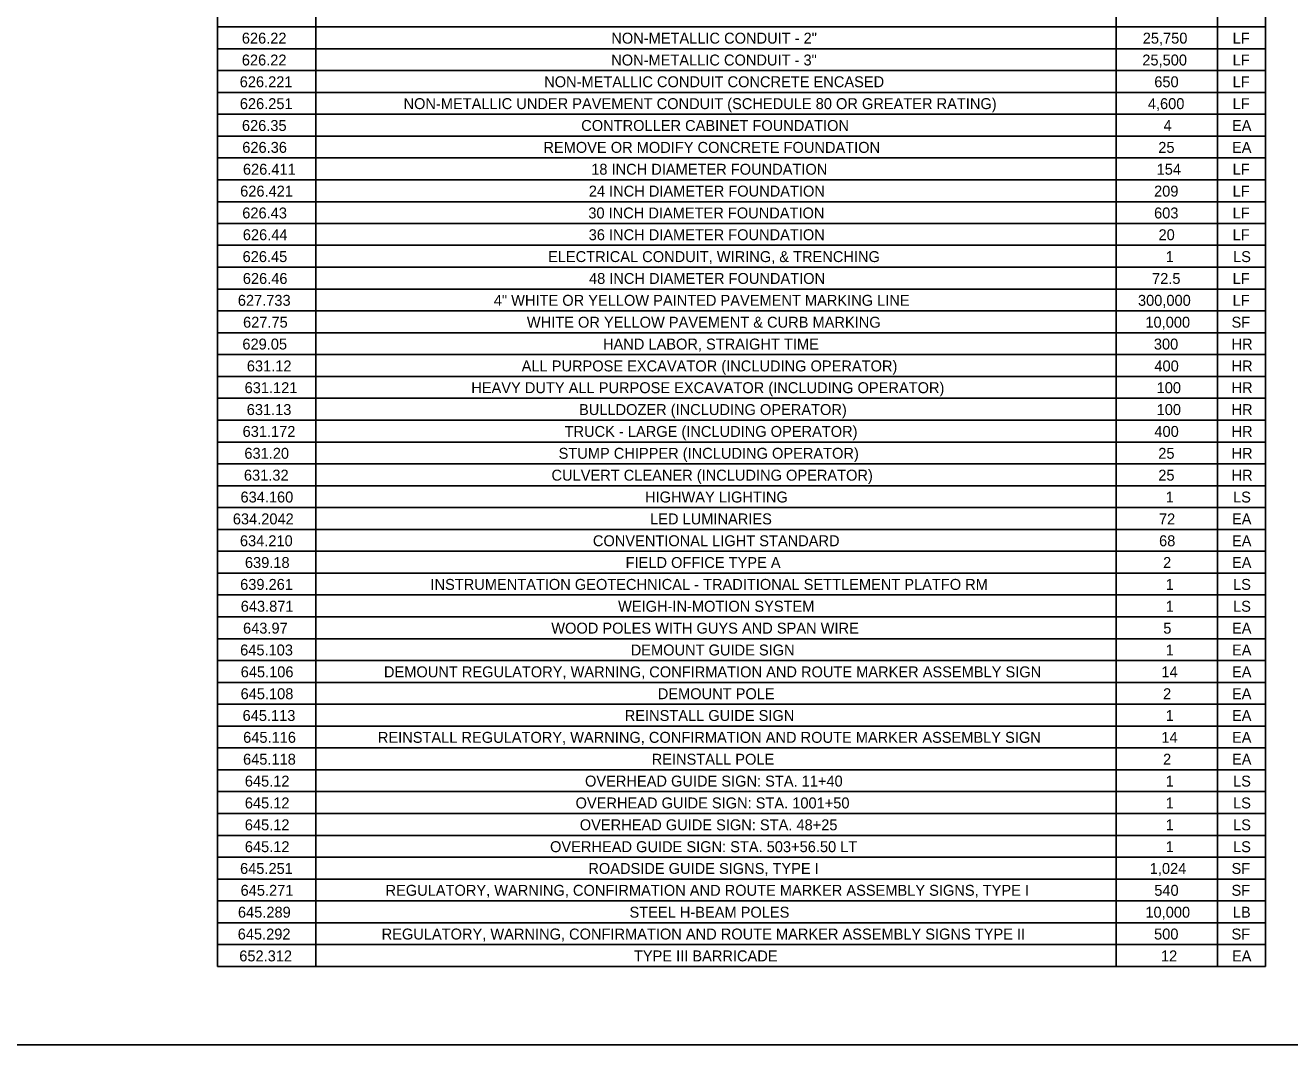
# Model space of a CAD drawing. Extents: x -18.7 to 5.6, y -2.7 to 4.
# Drawn here: x -15.505 to -14.366, y 2.172 to 3.09 of the extents above; entities that cross this region are included whole.
import ezdxf

# ---------------------------------------------------------------- set-up
doc = ezdxf.new("R2010")
doc.units = 0
doc.layers.add('ANNOTATION', color=7, linetype='Continuous')
doc.layers.add('BORDER', color=7, linetype='Continuous')

msp = doc.modelspace()

# ---------------------------------------------------------------- linework, layer by layer
at = {"layer": 'ANNOTATION'}
msp.add_lwpolyline([(-17.663, 4.0141), (-13.3075, 4.0141), (-13.3075, 2.1719), (-17.663, 2.1719)], close=True, dxfattribs=at)
at = {"layer": 'BORDER'}
for p, q in [((-15.2435, 3.9551), (-15.2435, 2.2424)), ((-14.5222, 3.9551), (-14.5222, 2.2424)), ((-14.4308, 3.9551), (-14.4308, 2.2424)), ((-15.3321, 3.0889), (-14.3878, 3.0889)), ((-15.3321, 3.0692), (-14.3878, 3.0692)), ((-15.3321, 3.0495), (-14.3878, 3.0495)), ((-15.3321, 3.0299), (-14.3878, 3.0299)), ((-15.3321, 3.0102), (-14.3878, 3.0102)), ((-15.3321, 2.9905), (-14.3878, 2.9905)), ((-15.3321, 2.9708), (-14.3878, 2.9708)), ((-15.3321, 2.9511), (-14.3878, 2.9511)), ((-15.3321, 2.9314), (-14.3878, 2.9314)), ((-15.3321, 2.9117), (-14.3878, 2.9117)), ((-15.3321, 2.8921), (-14.3878, 2.8921)), ((-15.3321, 2.8724), (-14.3878, 2.8724)), ((-15.3321, 2.8527), (-14.3878, 2.8527)), ((-15.3321, 2.833), (-14.3878, 2.833)), ((-15.3321, 2.8133), (-14.3878, 2.8133)), ((-15.3321, 2.7936), (-14.3878, 2.7936)), ((-15.3321, 2.7739), (-14.3878, 2.7739)), ((-15.3321, 2.7543), (-14.3878, 2.7543)), ((-15.3321, 2.7346), (-14.3878, 2.7346)), ((-15.3321, 2.7149), (-14.3878, 2.7149)), ((-15.3321, 2.6952), (-14.3878, 2.6952)), ((-15.3321, 2.6755), (-14.3878, 2.6755)), ((-15.3321, 2.6558), (-14.3878, 2.6558)), ((-15.3321, 2.6361), (-14.3878, 2.6361)), ((-15.3321, 2.6165), (-14.3878, 2.6165)), ((-15.3321, 2.5968), (-14.3878, 2.5968)), ((-15.3321, 2.5771), (-14.3878, 2.5771)), ((-15.3321, 2.5574), (-14.3878, 2.5574)), ((-15.3321, 2.5377), (-14.3878, 2.5377)), ((-15.3321, 2.518), (-14.3878, 2.518)), ((-15.3321, 2.4983), (-14.3878, 2.4983)), ((-15.3321, 2.4787), (-14.3878, 2.4787)), ((-15.3321, 2.459), (-14.3878, 2.459)), ((-15.3321, 2.4393), (-14.3878, 2.4393)), ((-15.3321, 2.4196), (-14.3878, 2.4196)), ((-15.3321, 2.3999), (-14.3878, 2.3999)), ((-15.3321, 2.3802), (-14.3878, 2.3802)), ((-15.3321, 2.3605), (-14.3878, 2.3605)), ((-15.3321, 2.3408), (-14.3878, 2.3408)), ((-15.3321, 2.3212), (-14.3878, 2.3212)), ((-15.3321, 2.3015), (-14.3878, 2.3015)), ((-15.3321, 2.2818), (-14.3878, 2.2818)), ((-15.3321, 2.2621), (-14.3878, 2.2621)), ((-15.3321, 2.2424), (-14.3878, 2.2424))]:
    msp.add_line(p, q, dxfattribs=at)
msp.add_lwpolyline([(-15.3321, 3.9748), (-14.3878, 3.9748), (-14.3878, 2.2424), (-15.3321, 2.2424)], close=True, dxfattribs=at)

# ---------------------------------------------------------------- texts
at = {"layer": 'ANNOTATION'}
for s, height, p in [('626.22', 0.00984, (-15.3103, 3.0738)), ('NON-METALLIC CONDUIT - 2"', 0.009843, (-14.9773, 3.0738)), ('25,750', 0.00984, (-14.4983, 3.0738)), ('LF', 0.00984, (-14.4173, 3.0738)), ('626.22', 0.00984, (-15.3103, 3.0541)), ('NON-METALLIC CONDUIT - 3"', 0.009843, (-14.9774, 3.0541)), ('25,500', 0.00984, (-14.4987, 3.0541)), ('LF', 0.00984, (-14.4173, 3.0541)), ('626.221', 0.00984, (-15.3122, 3.0345)), ('NON-METALLIC CONDUIT CONCRETE ENCASED', 0.009843, (-15.0378, 3.0345)), ('650', 0.00984, (-14.4879, 3.0345)), ('LF', 0.00984, (-14.4173, 3.0345)), ('626.251', 0.00984, (-15.3121, 3.0148)), ('NON-METALLIC UNDER PAVEMENT CONDUIT (SCHEDULE 80 OR GREATER RATING)', 0.009843, (-15.1646, 3.0148)), ('4,600', 0.00984, (-14.4937, 3.0148)), ('LF', 0.00984, (-14.4173, 3.0148)), ('626.35', 0.00984, (-15.3102, 2.9951)), ('CONTROLLER CABINET FOUNDATION', 0.009843, (-15.0044, 2.9951)), ('4', 0.00984, (-14.4796, 2.9951)), ('EA', 0.00984, (-14.4179, 2.9951)), ('626.36', 0.00984, (-15.3099, 2.9754)), ('REMOVE OR MODIFY CONCRETE FOUNDATION', 0.009843, (-15.0385, 2.9754)), ('25', 0.00984, (-14.4843, 2.9754)), ('EA', 0.00984, (-14.4179, 2.9754)), ('626.411', 0.00984, (-15.3093, 2.9557)), ('18 INCH DIAMETER FOUNDATION', 0.009843, (-14.9954, 2.9557)), ('154', 0.00984, (-14.4858, 2.9557)), ('LF', 0.00984, (-14.4173, 2.9557)), ('626.421', 0.00984, (-15.3118, 2.936)), ('24 INCH DIAMETER FOUNDATION', 0.009843, (-14.9976, 2.936)), ('209', 0.00984, (-14.4881, 2.936)), ('LF', 0.00984, (-14.4173, 2.936)), ('626.43', 0.00984, (-15.3099, 2.9163)), ('30 INCH DIAMETER FOUNDATION', 0.009843, (-14.998, 2.9163)), ('603', 0.00984, (-14.4881, 2.9163)), ('LF', 0.00984, (-14.4173, 2.9163)), ('626.44', 0.00984, (-15.3094, 2.8967)), ('36 INCH DIAMETER FOUNDATION', 0.009843, (-14.9977, 2.8967)), ('20', 0.00984, (-14.4841, 2.8967)), ('LF', 0.00984, (-14.4173, 2.8967)), ('626.45', 0.00984, (-15.3096, 2.877)), ('ELECTRICAL CONDUIT, WIRING, & TRENCHING', 0.009843, (-15.0343, 2.877)), ('1', 0.00984, (-14.4776, 2.877)), ('LS', 0.00984, (-14.4169, 2.877)), ('626.46', 0.00984, (-15.3094, 2.8573)), ('48 INCH DIAMETER FOUNDATION', 0.009843, (-14.9974, 2.8573)), ('72.5', 0.00984, (-14.4899, 2.8573)), ('LF', 0.00984, (-14.4173, 2.8573)), ('627.733', 0.00984, (-15.3139, 2.8376)), ('4" WHITE OR YELLOW PAINTED PAVEMENT MARKING LINE', 0.009843, (-15.0832, 2.8376)), ('300,000', 0.00984, (-14.5026, 2.8376)), ('LF', 0.00984, (-14.4173, 2.8376)), ('627.75', 0.00984, (-15.3092, 2.8179)), ('WHITE OR YELLOW PAVEMENT & CURB MARKING', 0.009843, (-15.0534, 2.8179)), ('10,000', 0.00984, (-14.4959, 2.8179)), ('SF', 0.00984, (-14.4183, 2.8179)), ('629.05', 0.00984, (-15.3098, 2.7982)), ('HAND LABOR, STRAIGHT TIME', 0.009843, (-14.9848, 2.7982)), ('300', 0.00984, (-14.4883, 2.7982)), ('HR', 0.00984, (-14.4183, 2.7982)), ('631.12', 0.00984, (-15.3058, 2.7785)), ('ALL PURPOSE EXCAVATOR (INCLUDING OPERATOR)', 0.009843, (-15.0581, 2.7785)), ('400', 0.00984, (-14.4878, 2.7785)), ('HR', 0.00984, (-14.4183, 2.7785)), ('631.121', 0.00984, (-15.3078, 2.7589)), ('HEAVY DUTY ALL PURPOSE EXCAVATOR (INCLUDING OPERATOR)', 0.009843, (-15.1035, 2.7589)), ('100', 0.00984, (-14.4858, 2.7589)), ('HR', 0.00984, (-14.4183, 2.7589)), ('631.13', 0.00984, (-15.3059, 2.7392)), ('BULLDOZER (INCLUDING OPERATOR)', 0.009843, (-15.0064, 2.7392)), ('100', 0.00984, (-14.4858, 2.7392)), ('HR', 0.00984, (-14.4183, 2.7392)), ('631.172', 0.00984, (-15.3096, 2.7195)), ('TRUCK - LARGE (INCLUDING OPERATOR)', 0.009843, (-15.0194, 2.7195)), ('400', 0.00984, (-14.4878, 2.7195)), ('HR', 0.00984, (-14.4183, 2.7195)), ('631.20', 0.00984, (-15.308, 2.6998)), ('STUMP CHIPPER (INCLUDING OPERATOR)', 0.009843, (-15.0248, 2.6998)), ('25', 0.00984, (-14.4843, 2.6998)), ('HR', 0.00984, (-14.4183, 2.6998)), ('631.32', 0.00984, (-15.3084, 2.6801)), ('CULVERT CLEANER (INCLUDING OPERATOR)', 0.009843, (-15.0312, 2.6801)), ('25', 0.00984, (-14.4843, 2.6801)), ('HR', 0.00984, (-14.4183, 2.6801)), ('634.160', 0.00984, (-15.3115, 2.6604)), ('HIGHWAY LIGHTING', 0.009843, (-14.9469, 2.6604)), ('1', 0.00984, (-14.4776, 2.6604)), ('LS', 0.00984, (-14.4169, 2.6604)), ('634.2042', 0.00984, (-15.3184, 2.6407)), ('LED LUMINARIES', 0.009843, (-14.9423, 2.6407)), ('72', 0.00984, (-14.4837, 2.6407)), ('EA', 0.00984, (-14.4179, 2.6407)), ('634.210', 0.00984, (-15.312, 2.621)), ('CONVENTIONAL LIGHT STANDARD', 0.009843, (-14.9939, 2.621)), ('68', 0.00984, (-14.4836, 2.621)), ('EA', 0.00984, (-14.4179, 2.621)), ('639.18', 0.00984, (-15.3075, 2.6014)), ('FIELD OFFICE TYPE A', 0.009843, (-14.9644, 2.6014)), ('2', 0.00984, (-14.48, 2.6014)), ('EA', 0.00984, (-14.4179, 2.6014)), ('639.261', 0.00984, (-15.3118, 2.5817)), ('INSTRUMENTATION GEOTECHNICAL - TRADITIONAL SETTLEMENT PLATFO RM', 0.009843, (-15.1403, 2.5817)), ('1', 0.00984, (-14.4776, 2.5817)), ('LS', 0.00984, (-14.4169, 2.5817)), ('643.871', 0.00984, (-15.3113, 2.562)), ('WEIGH-IN-MOTION SYSTEM', 0.009843, (-14.9712, 2.562)), ('1', 0.00984, (-14.4776, 2.562)), ('LS', 0.00984, (-14.4169, 2.562)), ('643.97', 0.00984, (-15.3092, 2.5423)), ('WOOD POLES WITH GUYS AND SPAN WIRE', 0.009843, (-15.0314, 2.5423)), ('5', 0.00984, (-14.4798, 2.5423)), ('EA', 0.00984, (-14.4179, 2.5423)), ('645.103', 0.00984, (-15.3118, 2.5226)), ('DEMOUNT GUIDE SIGN', 0.009843, (-14.9598, 2.5226)), ('1', 0.00984, (-14.4776, 2.5226)), ('EA', 0.00984, (-14.4179, 2.5226)), ('645.106', 0.00984, (-15.3113, 2.5029)), ('DEMOUNT REGULATORY, WARNING, CONFIRMATION AND ROUTE MARKER ASSEMBLY SIGN', 0.009843, (-15.1822, 2.5029)), ('14', 0.00984, (-14.4815, 2.5029)), ('EA', 0.00984, (-14.4179, 2.5029)), ('645.108', 0.00984, (-15.3114, 2.4832)), ('DEMOUNT POLE', 0.009843, (-14.9354, 2.4832)), ('2', 0.00984, (-14.48, 2.4832)), ('EA', 0.00984, (-14.4179, 2.4832)), ('645.113', 0.00984, (-15.3096, 2.4636)), ('REINSTALL GUIDE SIGN', 0.009843, (-14.9652, 2.4636)), ('1', 0.00984, (-14.4776, 2.4636)), ('EA', 0.00984, (-14.4179, 2.4636)), ('645.116', 0.00984, (-15.3091, 2.4439)), ('REINSTALL REGULATORY, WARNING, CONFIRMATION AND ROUTE MARKER ASSEMBLY SIGN', 0.009843, (-15.1877, 2.4439)), ('14', 0.00984, (-14.4815, 2.4439)), ('EA', 0.00984, (-14.4179, 2.4439)), ('645.118', 0.00984, (-15.3092, 2.4242)), ('REINSTALL POLE', 0.009843, (-14.9409, 2.4242)), ('2', 0.00984, (-14.48, 2.4242)), ('EA', 0.00984, (-14.4179, 2.4242)), ('645.12', 0.00984, (-15.3076, 2.4045)), ('OVERHEAD GUIDE SIGN: STA. 11+40', 0.009843, (-15.001, 2.4045)), ('1', 0.00984, (-14.4776, 2.4045)), ('LS', 0.00984, (-14.4169, 2.4045)), ('645.12', 0.00984, (-15.3076, 2.3848)), ('OVERHEAD GUIDE SIGN: STA. 1001+50', 0.009843, (-15.0095, 2.3848)), ('1', 0.00984, (-14.4776, 2.3848)), ('LS', 0.00984, (-14.4169, 2.3848)), ('645.12', 0.00984, (-15.3076, 2.3651)), ('OVERHEAD GUIDE SIGN: STA. 48+25', 0.009843, (-15.0057, 2.3651)), ('1', 0.00984, (-14.4776, 2.3651)), ('LS', 0.00984, (-14.4169, 2.3651)), ('645.12', 0.00984, (-15.3076, 2.3454)), ('OVERHEAD GUIDE SIGN: STA. 503+56.50 LT', 0.009843, (-15.0325, 2.3454)), ('1', 0.00984, (-14.4776, 2.3454)), ('LS', 0.00984, (-14.4169, 2.3454)), ('645.251', 0.00984, (-15.3119, 2.3258)), ('ROADSIDE GUIDE SIGNS, TYPE I', 0.009843, (-14.998, 2.3258)), ('1,024', 0.00984, (-14.492, 2.3258)), ('SF', 0.00984, (-14.4183, 2.3258)), ('645.271', 0.00984, (-15.3114, 2.3061)), ('REGULATORY, WARNING, CONFIRMATION AND ROUTE MARKER ASSEMBLY SIGNS, TYPE I', 0.009843, (-15.1808, 2.3061)), ('540', 0.00984, (-14.4879, 2.3061)), ('SF', 0.00984, (-14.4183, 2.3061)), ('645.289', 0.00984, (-15.3138, 2.2864)), ('STEEL H-BEAM POLES', 0.009843, (-14.9609, 2.2864)), ('10,000', 0.00984, (-14.4959, 2.2864)), ('LB', 0.00984, (-14.4171, 2.2864)), ('645.292', 0.00984, (-15.314, 2.2667)), ('REGULATORY, WARNING, CONFIRMATION AND ROUTE MARKER ASSEMBLY SIGNS TYPE II', 0.009843, (-15.1843, 2.2667)), ('500', 0.00984, (-14.4881, 2.2667)), ('SF', 0.00984, (-14.4183, 2.2667)), ('652.312', 0.00984, (-15.3126, 2.247)), ('TYPE III BARRICADE', 0.009843, (-14.9569, 2.247)), ('12', 0.00984, (-14.4819, 2.247)), ('EA', 0.00984, (-14.4179, 2.247))]:
    msp.add_text(s, height=height, dxfattribs=at).set_placement(p)

doc.saveas('drawing.dxf')
